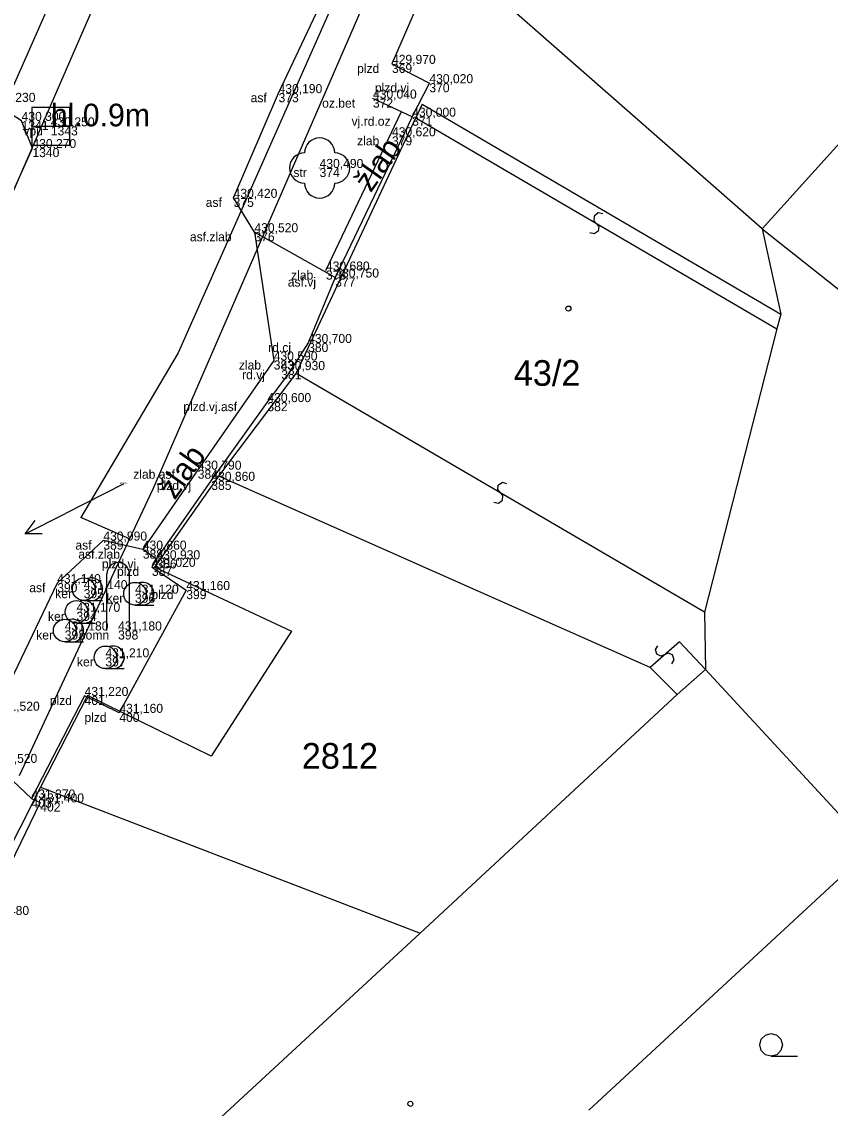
# Model space of a CAD drawing. Extents: x -747792 to -745414, y -1093712 to -1091463.
# Drawn here: x -746623.4 to -746596.59, y -1093002.59 to -1092966.57 of the extents above; entities that cross this region are included whole.
import ezdxf

# ---------------------------------------------------------------- set-up
doc = ezdxf.new("R2010")
doc.units = 0
for name, color, linetype in [('Budovy', 7, 'Continuous'), ('Doplňkové značky', 7, 'Continuous'), ('Hladina', 7, 'Continuous'), ('Koleje_dopravní prvky', 7, 'Continuous'), ('Kultury', 7, 'Continuous'), ('Nezařazené objekty', 7, 'Continuous'), ('Nivelační značky_hrany', 7, 'Continuous'), ('Názvy obcí_ulic', 7, 'Continuous'), ('Ploty_opěrné zdi', 7, 'Continuous'), ('Popisy objektů_povrchů', 7, 'Continuous'), ('Pracovní_bod JDTM STC_VC - výška', 7, 'Continuous'), ('Pracovní_bod PPBP - výška', 7, 'Continuous'), ('Pracovní_bod PPBP - číslo', 7, 'Continuous'), ('Pracovní_bod ZPBP', 7, 'Continuous'), ('Pracovní_bod ZPBP - číslo', 7, 'Continuous'), ('Rozhraní ploch', 7, 'Continuous'), ('Stromy_porost', 7, 'Continuous'), ('Výškopis', 7, 'Continuous'), ('Čísla popisná_parcelní', 7, 'Continuous')]:
    doc.layers.add(name, color=color, linetype=linetype)

msp = doc.modelspace()

# ---------------------------------------------------------------- linework, layer by layer
at = {"layer": 'Budovy'}
msp.add_lwpolyline([(-746598.55, -1093000.86), (-746598.74, -1093000.81), (-746598.875, -1093000.67), (-746598.925, -1093000.485), (-746598.875, -1093000.3), (-746598.74, -1093000.16), (-746598.55, -1093000.11), (-746598.36, -1093000.16), (-746598.225, -1093000.3), (-746598.175, -1093000.485), (-746598.225, -1093000.67), (-746598.36, -1093000.81), (-746598.55, -1093000.86), (-746597.675, -1093000.86)], dxfattribs=at)
at = {"layer": 'Doplňkové značky'}
for points in [[(-746620.01, -1092981.89), (-746621.94, -1092982.87)], [(-746623.278, -1092983.549), (-746621.94, -1092982.87)], [(-746622.719, -1092983.546), (-746623.278, -1092983.549), (-746622.945, -1092983.1)]]:
    msp.add_lwpolyline(points, dxfattribs=at)
at = {"layer": 'Hladina'}
for p, q in [((-746611.12, -1092967.97), (-746611.12, -1092967.97)), ((-746609.88, -1092968.61), (-746609.88, -1092968.61)), ((-746614.88, -1092968.94), (-746614.88, -1092968.94)), ((-746611.75, -1092969.12), (-746611.75, -1092969.12)), ((-746610.45, -1092969.72), (-746610.45, -1092969.72)), ((-746622.43, -1092970.04), (-746622.43, -1092970.04)), ((-746611.12, -1092970.37), (-746611.12, -1092970.37)), ((-746623.04, -1092970.76), (-746623.04, -1092970.76)), ((-746613.52, -1092971.42), (-746613.52, -1092971.42)), ((-746616.37, -1092972.41), (-746616.37, -1092972.41)), ((-746615.68, -1092973.55), (-746615.68, -1092973.55)), ((-746613.31, -1092974.82), (-746613.31, -1092974.82)), ((-746613, -1092975.05), (-746613, -1092975.05)), ((-746613.9, -1092977.22), (-746613.9, -1092977.22)), ((-746615.04, -1092977.8), (-746615.04, -1092977.8)), ((-746614.79, -1092978.12), (-746614.79, -1092978.12)), ((-746615.25, -1092979.18), (-746615.25, -1092979.18)), ((-746617.56, -1092981.42), (-746617.56, -1092981.42)), ((-746617.11, -1092981.79), (-746617.11, -1092981.79)), ((-746620.69, -1092983.77), (-746620.69, -1092983.77)), ((-746619.38, -1092984.07), (-746619.38, -1092984.07)), ((-746618.93, -1092984.39), (-746618.93, -1092984.39)), ((-746619.08, -1092984.64), (-746619.08, -1092984.64)), ((-746622.22, -1092985.18), (-746622.22, -1092985.18)), ((-746621.34, -1092985.38), (-746621.34, -1092985.38)), ((-746619.64, -1092985.53), (-746619.64, -1092985.53)), ((-746617.94, -1092985.41), (-746617.94, -1092985.41)), ((-746621.58, -1092986.13), (-746621.58, -1092986.13)), ((-746621.97, -1092986.75), (-746621.97, -1092986.75)), ((-746620.2, -1092986.75), (-746620.2, -1092986.75)), ((-746620.62, -1092987.64), (-746620.62, -1092987.64)), ((-746621.31, -1092988.92), (-746621.31, -1092988.92)), ((-746620.16, -1092989.48), (-746620.16, -1092989.48)), ((-746623.07, -1092992.32), (-746623.07, -1092992.32)), ((-746622.78, -1092992.45), (-746622.78, -1092992.45))]:
    msp.add_line(p, q, dxfattribs=at)
at = {"layer": 'Kultury'}
for points in [[(-746610.33, -1092969.76), (-746598.36, -1092976.75)], [(-746604.134, -1092972.944), (-746604.289, -1092972.911), (-746604.419, -1092973.015), (-746604.427, -1092973.167), (-746604.262, -1092973.361), (-746604.281, -1092973.512), (-746604.415, -1092973.602), (-746604.556, -1092973.566)], [(-746600.76, -1092986.14), (-746614.3, -1092978.23)], [(-746607.741, -1092982.496), (-746607.586, -1092982.529), (-746607.456, -1092982.425), (-746607.448, -1092982.273), (-746607.613, -1092982.079), (-746607.594, -1092981.928), (-746607.46, -1092981.838), (-746607.319, -1092981.874)], [(-746601.59, -1092987.13), (-746602.56, -1092987.98)], [(-746601.847, -1092987.853), (-746601.767, -1092987.717), (-746601.824, -1092987.561), (-746601.965, -1092987.505), (-746602.202, -1092987.6), (-746602.339, -1092987.534), (-746602.382, -1092987.379), (-746602.303, -1092987.257)], [(-746601.59, -1092987.13), (-746600.73, -1092988.04)]]:
    msp.add_lwpolyline(points, dxfattribs=at)
at = {"layer": 'Nezařazené objekty'}
for points in [[(-746596.93, -1092949.97), (-746599.18, -1092953.22), (-746603.68, -1092950.86), (-746611.12, -1092967.97), (-746609.88, -1092968.61)], [(-746610.45, -1092969.72), (-746611.75, -1092969.12)], [(-746613.9, -1092977.22), (-746614.61, -1092978.32)], [(-746617.11, -1092981.79), (-746615.25, -1092979.18)], [(-746618.93, -1092984.39), (-746619.08, -1092984.64), (-746617.94, -1092985.41), (-746620.16, -1092989.48), (-746621.31, -1092988.92), (-746623.07, -1092992.32), (-746622.78, -1092992.45)]]:
    msp.add_lwpolyline(points, dxfattribs=at)
at = {"layer": 'Nivelační značky_hrany'}
for points in [[(-746613, -1092975.05), (-746615.68, -1092973.55), (-746616.37, -1092972.41), (-746614.88, -1092968.94), (-746611.1, -1092960.94), (-746602.86, -1092944.72), (-746601.02, -1092942.96), (-746597.95, -1092943.58)], [(-746627.54, -1092976.34), (-746626.43, -1092976.48), (-746625.44, -1092976.09), (-746623.04, -1092970.76), (-746623.4, -1092969.86), (-746624.39, -1092969.23)], [(-746618.93, -1092984.39), (-746619.38, -1092984.07), (-746620.69, -1092983.77), (-746622.22, -1092985.18), (-746624.25, -1092989.41), (-746624.33, -1092991.14), (-746623.07, -1092992.32)]]:
    msp.add_lwpolyline(points, dxfattribs=at)
at = {"layer": 'Názvy obcí_ulic'}
for p, q in [((-746620.575, -1092986.75), (-746620.575, -1092984.875)), ((-746619.825, -1092986.75), (-746619.825, -1092984.875))]:
    msp.add_line(p, q, dxfattribs=at)
msp.add_arc((-746620.2, -1092984.875), 0.375, 0, 180, dxfattribs=at)
at = {"layer": 'Ploty_opěrné zdi'}
for points in [[(-746605.27, -1092975.995), (-746605.22, -1092976.005), (-746605.195, -1092976.05), (-746605.185, -1092976.08), (-746605.195, -1092976.125), (-746605.235, -1092976.16), (-746605.27, -1092976.165), (-746605.315, -1092976.15), (-746605.345, -1092976.12), (-746605.355, -1092976.08), (-746605.345, -1092976.035), (-746605.305, -1092976)], [(-746610.51, -1093002.355), (-746610.46, -1093002.365), (-746610.435, -1093002.41), (-746610.425, -1093002.44), (-746610.435, -1093002.485), (-746610.475, -1093002.52), (-746610.51, -1093002.525), (-746610.555, -1093002.51), (-746610.585, -1093002.48), (-746610.595, -1093002.44), (-746610.585, -1093002.395), (-746610.545, -1093002.36)]]:
    msp.add_lwpolyline(points, close=True, dxfattribs=at)
at = {"layer": 'Popisy objektů_povrchů'}
msp.add_lwpolyline([(-746610.45, -1092969.72), (-746613, -1092975.05)], dxfattribs=at)
at = {"layer": 'Pracovní_bod JDTM STC_VC - výška'}
msp.add_circle((-746613.52, -1092971.42), 0.0005, dxfattribs=at)
for centre, start, end in [((-746613.52, -1092970.92), 0, 180), ((-746614.02, -1092971.42), 90, 270), ((-746613.02, -1092971.42), 270, 90), ((-746613.52, -1092971.92), 180, 360)]:
    msp.add_arc(centre, 0.5, start, end, dxfattribs=at)
at = {"layer": 'Pracovní_bod PPBP - výška'}
for points in [[(-746610.45, -1092969.72), (-746609.88, -1092968.61)], [(-746613, -1092975.05), (-746613.9, -1092977.22)], [(-746615.25, -1092979.18), (-746614.61, -1092978.32)], [(-746618.93, -1092984.39), (-746617.11, -1092981.79)], [(-746622.78, -1092992.45), (-746624.6, -1092996.18)]]:
    msp.add_lwpolyline(points, dxfattribs=at)
at = {"layer": 'Pracovní_bod PPBP - číslo'}
for p, q in [((-746621.34, -1092985.755), (-746620.715, -1092985.755)), ((-746619.64, -1092985.905), (-746619.015, -1092985.905)), ((-746621.58, -1092986.505), (-746620.955, -1092986.505)), ((-746621.97, -1092987.125), (-746621.345, -1092987.125)), ((-746620.62, -1092988.015), (-746619.995, -1092988.015))]:
    msp.add_line(p, q, dxfattribs=at)
for centre in [(-746621.34, -1092985.38), (-746619.64, -1092985.53), (-746621.58, -1092986.13), (-746621.97, -1092986.75), (-746620.62, -1092987.64)]:
    msp.add_circle(centre, 0.375, dxfattribs=at)
for centre in [(-746621.09, -1092985.38), (-746619.39, -1092985.53), (-746621.33, -1092986.13), (-746621.72, -1092986.75), (-746620.37, -1092987.64)]:
    msp.add_arc(centre, 0.375, 249.4944, 109.0474, dxfattribs=at)
at = {"layer": 'Pracovní_bod ZPBP'}
for points in [[(-746613.31, -1092974.82), (-746610.82, -1092969.57)], [(-746615.68, -1092973.55), (-746615.04, -1092977.8), (-746617.56, -1092981.42), (-746619.38, -1092984.07)]]:
    msp.add_lwpolyline(points, dxfattribs=at)
at = {"layer": 'Stromy_porost'}
for points in [[(-746616.96, -1092956.74), (-746628.34, -1092982.88)], [(-746586.42, -1092959.67), (-746598.85, -1092973.44)], [(-746611.48, -1092962.35), (-746618.21, -1092977.55)], [(-746610.76, -1092962.98), (-746619.05, -1092982.07)], [(-746598.85, -1092973.44), (-746610.76, -1092962.98)], [(-746622.01, -1092964.92), (-746629.27, -1092981.35)], [(-746610.12, -1092969.31), (-746610.33, -1092969.76)], [(-746610.12, -1092969.31), (-746598.23, -1092976.27)], [(-746614.3, -1092978.23), (-746610.33, -1092969.76)], [(-746598.85, -1092973.44), (-746598.23, -1092976.27)], [(-746598.85, -1092973.44), (-746589.08, -1092981.17)], [(-746598.23, -1092976.27), (-746598.36, -1092976.75)], [(-746598.36, -1092976.75), (-746600.76, -1092986.14)], [(-746618.21, -1092977.55), (-746621.44, -1092983.01)], [(-746616.86, -1092981.63), (-746614.3, -1092978.23)], [(-746618.98, -1092984.65), (-746616.86, -1092981.63)], [(-746602.56, -1092987.98), (-746616.86, -1092981.63)], [(-746619.05, -1092982.07), (-746619.82, -1092983.71)], [(-746619.82, -1092983.71), (-746621.44, -1092983.01)], [(-746619.82, -1092983.71), (-746623.48, -1092991.57)], [(-746618.98, -1092984.65), (-746614.45, -1092986.77)], [(-746600.76, -1092986.14), (-746600.73, -1092988.04)], [(-746614.45, -1092986.77), (-746617.11, -1092990.91)], [(-746601.66, -1092988.87), (-746602.56, -1092987.98)], [(-746600.73, -1092988.04), (-746601.66, -1092988.87)], [(-746600.73, -1092988.04), (-746595.23, -1092993.99)], [(-746621.22, -1092988.91), (-746622.77, -1092991.94)], [(-746617.11, -1092990.91), (-746621.22, -1092988.91)], [(-746601.66, -1092988.87), (-746610.19, -1092996.78)], [(-746622.77, -1092991.94), (-746634.45, -1093015.09)], [(-746622.77, -1092991.94), (-746610.19, -1092996.78)], [(-746595.89, -1092994.6), (-746604.59, -1093002.65)], [(-746610.19, -1092996.78), (-746619.71, -1093005.59)]]:
    msp.add_lwpolyline(points, dxfattribs=at)
at = {"layer": 'Čísla popisná_parcelní'}
for p, q in [((-746621.804, -1092969.413), (-746623.056, -1092969.413)), ((-746623.056, -1092969.413), (-746623.056, -1092970.667)), ((-746621.804, -1092970.667), (-746621.804, -1092969.413)), ((-746623.056, -1092970.039), (-746621.806, -1092970.039)), ((-746623.056, -1092970.667), (-746621.804, -1092970.667))]:
    msp.add_line(p, q, dxfattribs=at)

# ---------------------------------------------------------------- texts
at = {"layer": 'Koleje_dopravní prvky'}
for s, height, p in [('43/2', 0.85, (-746607.082, -1092978.64)), ('2761/24', 0.05, (-746620.144, -1092981.89)), ('2812', 0.85, (-746614.11, -1092991.33))]:
    msp.add_text(s, height=height, dxfattribs=at).set_placement(p)
at = {"layer": 'Pracovní_bod ZPBP - číslo'}
msp.add_text('hl.0.9m', height=0.75, dxfattribs=at).set_placement((-746622.43, -1092970.04))
for p in [(-746611.824, -1092972.259), (-746618.322, -1092982.448)]:
    msp.add_text('žlab', height=0.75, rotation=54.6731, dxfattribs=at).set_placement(p)
at = {"layer": 'Rozhraní ploch'}
for s, p in [(' plzd', (-746612.388, -1092968.27)), ('369', (-746611.12, -1092968.27)), (' plzd.vj', (-746611.798, -1092968.91)), ('370', (-746609.88, -1092968.91)), (' asf', (-746615.917, -1092969.24)), ('373', (-746614.88, -1092969.24)), (' oz.bet', (-746613.547, -1092969.42)), ('372', (-746611.75, -1092969.42)), (' vj.rd.oz', (-746612.571, -1092970.02)), ('371', (-746610.45, -1092970.02)), ('1341', (-746623.4, -1092970.16)), (' vpu', (-746623.453, -1092970.34)), ('1343', (-746622.43, -1092970.34)), (' zlab', (-746612.388, -1092970.67)), ('379', (-746611.12, -1092970.67)), ('1340', (-746623.04, -1092971.06)), (' str', (-746614.498, -1092971.72)), ('374', (-746613.52, -1092971.72)), (' asf', (-746617.407, -1092972.71)), ('375', (-746616.37, -1092972.71)), (' asf.zlab', (-746617.931, -1092973.85)), ('376', (-746615.68, -1092973.85)), (' zlab', (-746614.578, -1092975.12)), ('378', (-746613.31, -1092975.12)), (' asf.vj', (-746614.686, -1092975.35)), ('377', (-746613, -1092975.35)), (' rd.cj', (-746615.336, -1092977.52)), ('380', (-746613.9, -1092977.52)), (' zlab', (-746616.308, -1092978.1)), (' rd.vj', (-746616.2, -1092978.42)), ('383', (-746615.04, -1092978.1)), ('381', (-746614.79, -1092978.42)), (' plzd.vj.asf', (-746618.15, -1092979.48)), ('382', (-746615.25, -1092979.48)), (' zlab.asf', (-746619.811, -1092981.72)), ('384', (-746617.56, -1092981.72)), (' plzd.vj', (-746619.028, -1092982.09)), ('385', (-746617.11, -1092982.09)), (' asf', (-746621.727, -1092984.07)), ('389', (-746620.69, -1092984.07)), (' asf.zlab', (-746621.631, -1092984.37)), ('388', (-746619.38, -1092984.37)), (' plzd.vj', (-746620.848, -1092984.69)), ('386', (-746618.93, -1092984.69)), (' plzd', (-746620.348, -1092984.94)), ('387', (-746619.08, -1092984.94)), (' asf', (-746623.257, -1092985.48)), ('390', (-746622.22, -1092985.48)), (' ker', (-746622.396, -1092985.68)), ('395', (-746621.34, -1092985.68)), (' ker', (-746620.696, -1092985.83)), ('396', (-746619.64, -1092985.83)), (' plzd', (-746619.208, -1092985.71)), ('399', (-746617.94, -1092985.71)), (' ker', (-746622.636, -1092986.43)), ('394', (-746621.58, -1092986.43)), (' ker', (-746623.026, -1092987.05)), ('393', (-746621.97, -1092987.05)), ('398', (-746620.2, -1092987.05)), (' pomn', (-746621.612, -1092987.05)), (' ker', (-746621.676, -1092987.94)), ('397', (-746620.62, -1092987.94)), (' plzd', (-746622.578, -1092989.22)), ('401', (-746621.31, -1092989.22)), (' plzd', (-746621.428, -1092989.78)), ('400', (-746620.16, -1092989.78)), ('403', (-746623.07, -1092992.62)), ('402', (-746622.78, -1092992.75))]:
    msp.add_text(s, height=0.3, dxfattribs=at).set_placement(p)
at = {"layer": 'Výškopis'}
for s, p in [('429,970', (-746611.12, -1092967.97)), ('430,020', (-746609.88, -1092968.61)), ('430,190', (-746614.88, -1092968.94)), ('430,230', (-746624.39, -1092969.23)), ('430,040', (-746611.75, -1092969.12)), ('430,000', (-746610.45, -1092969.72)), ('430,300', (-746623.4, -1092969.86)), ('430,250', (-746622.43, -1092970.04)), ('430,620', (-746611.12, -1092970.37)), ('430,270', (-746623.04, -1092970.76)), ('430,490', (-746613.52, -1092971.42)), ('430,420', (-746616.37, -1092972.41)), ('430,520', (-746615.68, -1092973.55)), ('430,680', (-746613.31, -1092974.82)), ('430,750', (-746613, -1092975.05)), ('430,700', (-746613.9, -1092977.22)), ('430,590', (-746615.04, -1092977.8)), ('430,930', (-746614.79, -1092978.12)), ('430,600', (-746615.25, -1092979.18)), ('430,790', (-746617.56, -1092981.42)), ('430,860', (-746617.11, -1092981.79)), ('430,990', (-746620.69, -1092983.77)), ('430,860', (-746619.38, -1092984.07)), ('430,930', (-746618.93, -1092984.39)), ('431,020', (-746619.08, -1092984.64)), ('431,140', (-746622.22, -1092985.18)), ('431,140', (-746621.34, -1092985.38)), ('431,120', (-746619.64, -1092985.53)), ('431,160', (-746617.94, -1092985.41)), ('431,170', (-746621.58, -1092986.13)), ('431,180', (-746621.97, -1092986.75)), ('431,180', (-746620.2, -1092986.75)), ('431,210', (-746620.62, -1092987.64)), ('431,220', (-746621.31, -1092988.92)), ('431,520', (-746624.25, -1092989.41)), ('431,160', (-746620.16, -1092989.48)), ('431,520', (-746624.33, -1092991.14)), ('431,370', (-746623.07, -1092992.32)), ('431,400', (-746622.78, -1092992.45)), ('431,480', (-746624.6, -1092996.18))]:
    msp.add_text(s, height=0.3, dxfattribs=at).set_placement(p)

doc.saveas('drawing.dxf')
